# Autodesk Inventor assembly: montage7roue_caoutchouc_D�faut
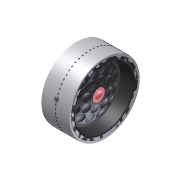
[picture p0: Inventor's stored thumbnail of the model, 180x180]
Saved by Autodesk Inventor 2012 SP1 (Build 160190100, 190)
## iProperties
Created: 2011-01
Part Number: montage7roue_caoutchouc_D�faut
Document SubType Name: Assembly
Designer: eric
Mass: 3043.31 g
Surface Area: 5165.36 cm^2
Volume: 3043.31 cm^3
Density: 1 g/cm^3
Author: eric
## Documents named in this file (15)
- D:\Cours\Inventor salle SI\chariot_de_golf_2008\chariot_de_golf_trolem\montage7roue_caoutchouc_Defaut.iam
- D:\Cours\Inventor salle SI\chariot_de_golf_2008\chariot_de_golf_trolem\7pneu_caoutchouc_Defaut.ipt
- D:\Cours\Inventor salle SI\chariot_de_golf_2008\chariot_de_golf_trolem\Rondelle_20x40x1_Defaut.ipt
- D:\Cours\Inventor salle SI\chariot_de_golf_2008\chariot_de_golf_trolem\8jante_bombee_Defaut.ipt
- D:\Cours\Inventor salle SI\chariot_de_golf_2008\chariot_de_golf_trolem\HF_20_26_16 _Defaut.iam
- D:\Cours\Inventor salle SI\chariot_de_golf_2008\chariot_de_golf_trolem\62goupille_epingle_Defaut.ipt
- D:\Cours\Inventor salle SI\chariot_de_golf_2008\chariot_de_golf_trolem\entretoise1_Defaut.ipt
- D:\Cours\Inventor salle SI\chariot_de_golf_2008\chariot_de_golf_trolem\Ecrou_H_M6_Defaut.ipt
- D:\Cours\Inventor salle SI\chariot_de_golf_2008\chariot_de_golf_trolem\anneauext18_Defaut.ipt
- D:\Cours\Inventor salle SI\chariot_de_golf_2008\chariot_de_golf_trolem\Bague_insert1_Defaut.ipt
- D:\Cours\Inventor salle SI\chariot_de_golf_2008\chariot_de_golf_trolem\8Vis_ M 6 x 40.ipt
- D:\Cours\Inventor salle SI\chariot_de_golf_2008\chariot_de_golf_trolem\Rondelle_20x32x1_Defaut.ipt
- D:\Cours\Inventor salle SI\chariot_de_golf_2008\chariot_de_golf_trolem\8bouchon_Defaut.ipt
- D:\Cours\Inventor salle SI\chariot_de_golf_2008\chariot_de_golf_trolem\Coussinet_cylindrique66_Defaut.ipt
- D:\Cours\Inventor salle SI\chariot_de_golf_2008\chariot_de_golf_trolem\cylindre_roue_simul.ipt
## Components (17 placed, 14 different names)
1. 7pneu_caoutchouc_Defaut:1 — Affleurement:1
2. Rondelle_20x40x1_Defaut:1
3. 8jante_bombee_Defaut:1
4. HF_20_26_16 _Defaut:1 [sub-assembly]
5. 62goupille_epingle_Defaut:1
6. entretoise1_Defaut:1
7. Ecrou_H_M6_Defaut:1
8. anneauext18_Defaut:1
9. Bague_insert1_Defaut:1
10. 8Vis_ M 6 x 40:1
11. Rondelle_20x32x1_Defaut:1
12. Ecrou_H_M6_Defaut:2
13. 8Vis_ M 6 x 40:2
14. 8bouchon_Defaut:1
15. Coussinet_cylindrique66_Defaut:1
16. anneauext18_Defaut:2
17. cylindre_roue_simul:1 — Affleurement:1
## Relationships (1: Flush 1)
- Affleurement:1 [Flush]: 7pneu_caoutchouc_Defaut:1 ↔ cylindre_roue_simul:1
